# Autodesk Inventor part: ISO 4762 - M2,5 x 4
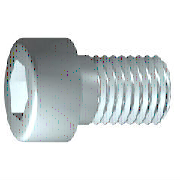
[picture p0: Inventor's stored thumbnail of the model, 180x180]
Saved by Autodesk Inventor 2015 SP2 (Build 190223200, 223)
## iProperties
IsCustomPart: 0
Created: 2012-02
Part Number: ISO 4762 - M2,5 x 4
Material: Stainless Steel, 440C
Description: Hexagon Socket Head Cap Screw
Document SubType Name: Modeling
Standard: ISO 4762
Designer: rYan
Standard Revision: Fourth edition 2004-03-01
Standards Organization: ISO
Language: en-US
Size Designation: M2,5 x 4
Categories: <MemberInstance><Categories><Category DisplayName="Fasteners" InternalName="e4da775c-781d-43d5-af7c-5136215cf5a6" Mnemonic="FSTN"><Category DisplayName="Bolts"
Density: 7.75 g/cm^3
Appearance: Halbpoliert
Author: rYan
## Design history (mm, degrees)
sketch "Sketch1"
  geometry: L1 (-0.733, 0)-(4, 0); L2 (4, 0)-(4, 1.25); L3 (4, 1.25)-(1.125, 1.25); L4 (1.125, 1.25)-(0.849, 1.25); L5 (0.849, 1.25)-(0, 1.25); L6 (0, 1.25)-(0, 2.25); L7 (0, 2.25)-(-2.5, 2.25); L8 (-2.5, 2.25)-(-2.5, 1.155); L9 (-2.5, 1.155)-(-1.4, 1.155); L10 (-1.4, 1.155)-(-0.733, 0); L11 (-3.8, 0)-(5.3, 0) reference; L12 (0, -0.45)-(0, 2.7) reference; L13 (1.125, 1.25)-(0, 1.25)
  constraints: 22 end point, 6 parallel, 2 collinear, 2 perpendicular, 1 horizontal, 1 point on line
  dimensions: "d1" = 2.875 distance from line of L3.end L2 (= GEL); "d2" = 0.27615 distance of L4.end L3.end (computed from GAL); "d3" = 2.5 distance between parallel lines of L8 L6 (= KOH); "d4" = 1.1 distance of L8.end L9.end (= INTI); "d5" = 60 deg angle of L10 L1; "d6" = 2.5 diameter of L3 L1 (= GD); "d7" = 2.5 diameter of L5 L1 (= BDM); "d8" = 2.3094 diameter of L9 L1 (= 1.1547 x SW); "d9" = 4.5 diameter of L7 L1 (= KOD); "d26" = 4 distance between parallel lines of L12 L2 (= NLG)
revolve "Body" sketch "Sketch1" stored, may be unused: angle "d10" = 90 deg
sketch "Sketch2"
  geometry: L1 (0, -3.15)-(0, 3.15) reference; L2 (-3.15, 0)-(3.15, 0) reference; L3 (1.155, 0)-(0.577, -1); L4 (0.577, -1)-(-0.577, -1); L5 (-0.577, -1)-(-1.155, 0); L6 (-1.155, 0)-(-0.577, 1); L7 (-0.577, 1)-(0.577, 1); L8 (0.577, 1)-(1.155, 0); 2 further points
  constraints: 12 end point, 1 coincident, 1 horizontal alignment, 1 point on line, 12 other
extrude "Slot" join sketch "Sketch2" stored distance "d11" = 10; taper "d12" = 0 deg
fillet "Fillet1" dims "d17" = 0.25 (= RR)
feature "Thread" dims "d13" = 2.875 (= GEL), "d14" = 0
chamfer "Chamfer1" distance "d15" = 0.27605 (= -0.5 x SPD + 0.5 x GD); stored, may be unused: second distance "d16" = 0.27605 (= GUL), angle "d27" = 45 deg
workplane "Work Plane1"
fillet "Fillet2" dims "d30" = 0.1 (= R)
body "Solid1"
other parameters: "GD" = 2.5 [user parameter; used in 2 equation terms], "NLG" = 4 [user parameter; used in 1 equation term], "GEL" = 2.875 [user parameter; used in 2 equation terms], "KOD" = 4.5 [user parameter; used in 1 equation term], "KOH" = 2.5 [user parameter; used in 1 equation term], "INTI" = 1.1 [user parameter; used in 1 equation term], "GAL" = 0.27605 (= 0.61345 x PTC) [user parameter; used in 1 equation term], "GUL" = 0.27605 (= 0.61345 x PTC) [user parameter; used in 1 equation term], "BDM" = 2.5 (= NND) [user parameter; used in 1 equation term], "SW" = 2 [user parameter; used in 2 equation terms], "RR" = 0.25 [user parameter; used in 1 equation term], "SPD" = 1.94789 (= NND - 1.2269 x PTC) [user parameter; used in 1 equation term], "d19" = 0, "d28" = 0, "d29" = 0, "R" = 0.1 [user parameter; used in 1 equation term], "TOA" = 30 deg [user parameter], "GD1" = 1.94789 (= THREADDIA - 1.2269 x PTC) [user parameter], "THREADDIA" = 2.5 [user parameter; used in 1 equation term], "FAWI" = 45 deg [user parameter], "TPU" = 22.22222 (computed from PTC) [user parameter], "PTC" = 0.45 [user parameter; used in 5 equation terms], "NND" = 2.5 [user parameter; used in 2 equation terms], "E0" = 2.31 (= 1.155 x SW) [user parameter]
